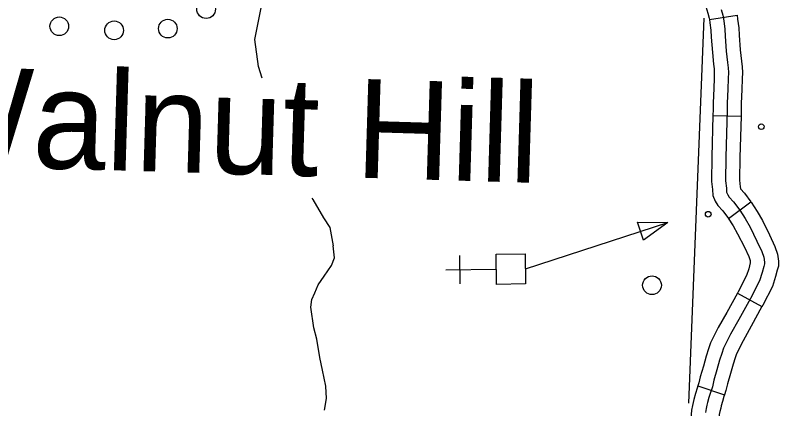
# Model space of a CAD drawing. Extents: x 653372 to 905732, y 627442 to 787275.
# Drawn here: x 722553 to 726614, y 759842 to 761946 of the extents above; entities that cross this region are included whole.
import ezdxf

# ---------------------------------------------------------------- set-up
doc = ezdxf.new("R2010")
doc.units = 0
for name, color, linetype in [('25', 7, 'Continuous'), ('32', 7, 'Continuous'), ('35', 7, 'Continuous'), ('5', 7, 'Continuous'), ('56', 7, 'Continuous'), ('57', 7, 'Continuous')]:
    doc.layers.add(name, color=color, linetype=linetype)

msp = doc.modelspace()

# ---------------------------------------------------------------- linework, layer by layer
at = {"layer": '32'}
for p, q in [((726264.3, 761922.8), (726412.4, 761946.2)), ((726283.8, 761410), (726433.7, 761406.1)), ((726366.7, 760858.7), (726486.6, 760948.9)), ((726414, 760460.5), (726545.6, 760388.4)), ((726203, 759965.3), (726345.2, 759917.6))]:
    msp.add_line(p, q, dxfattribs=at)
for points in [[(726211.6, 762073.5), (726239.8, 762015.5), (726242.1, 762008.5), (726245.6, 761993.2), (726255.9, 761957.5), (726263.1, 761930.4), (726264.3, 761922.8)], [(726328.2, 761977.5), (726336.6, 761945.8), (726341.4, 761915.5), (726346.5, 761872.1), (726348.9, 761833.5), (726355.1, 761753.9), (726361.8, 761693), (726364.5, 761665), (726365.9, 761639.1), (726365, 761608.1), (726363.3, 761551), (726359.9, 761475.5), (726359.6, 761440.9)], [(726412.4, 761946.2), (726415.7, 761925.7), (726421.2, 761878.9), (726423.7, 761838.7), (726429.8, 761760.9), (726436.4, 761700.8), (726439.4, 761670.7), (726441, 761640), (726439.9, 761605.8), (726438.2, 761548.2), (726434.9, 761473.5), (726434.6, 761439.6), (726433.7, 761406.1)], [(726264.3, 761922.8), (726267.1, 761905.2), (726271.8, 761865.4), (726274.1, 761828.3), (726280.4, 761746.8), (726287.2, 761685.2), (726289.7, 761659.4), (726290.8, 761638.3), (726290, 761610.3), (726288.3, 761553.8), (726284.9, 761477.5), (726284.6, 761442.2), (726283.8, 761410)], [(726359.6, 761440.9), (726353, 761187.8), (726350.7, 761061.3), (726355.2, 761021.9), (726356.7, 761000.2), (726362.7, 760986.5), (726370.2, 760973.4), (726393.7, 760947.7), (726426.7, 760903.8), (726456.1, 760858.6), (726481.9, 760813.5), (726518.9, 760738.7), (726545.1, 760682.9), (726554.9, 760651.8), (726559.2, 760626.7), (726558.9, 760616.7), (726554.9, 760602.5), (726546.7, 760570.6), (726532.5, 760525.3), (726484, 760432.1), (726422.7, 760320.2), (726378.2, 760241.5), (726340.2, 760165.8), (726330.8, 760138.2), (726319, 760102.1), (726304.6, 760050.4), (726288.6, 759994.4), (726280.4, 759960.3), (726270.2, 759929.9), (726262.2, 759902.2), (726254.3, 759875.3), (726251.7, 759861.1), (726247.6, 759844), (726243.4, 759822.7)], [(726283.8, 761410), (726278, 761189.5), (726275.6, 761057.7), (726280.5, 761015), (726282.8, 760982.1), (726295.6, 760952.8), (726309.2, 760929), (726335.9, 760899.7), (726366.7, 760858.7)], [(726433.7, 761406.1), (726428, 761186.1), (726425.7, 761064.9), (726429.9, 761028.8), (726430.6, 761018.9), (726431.2, 761017.8), (726451.5, 760995.6), (726486.6, 760948.9)], [(726487.7, 760947.4), (726488.7, 760946), (726520.1, 760897.6), (726548.1, 760848.8), (726586.5, 760771.3), (726615.1, 760710.2), (726628, 760669.4), (726634.3, 760631.9), (726633.5, 760605.2), (726627.3, 760583.1), (726618.9, 760550.1), (726602.1, 760496.5), (726550.1, 760396.7), (726545.6, 760388.4)], [(726364.7, 760861.5), (726392, 760819.5), (726415.7, 760778.1), (726451.4, 760706.1), (726475.1, 760655.5), (726481.8, 760634.2), (726483.3, 760625.2), (726482.4, 760621.9), (726474.6, 760591.1), (726462.9, 760554), (726417.8, 760467.4), (726414, 760460.5)], [(726414, 760460.5), (726357.2, 760356.7), (726312, 760276.8), (726270.9, 760194.9), (726259.7, 760162), (726247.2, 760123.9), (726232.4, 760070.7), (726216, 760013.4), (726208.3, 759981), (726203, 759965.3)], [(726545.6, 760388.4), (726488.3, 760283.7), (726444.4, 760206.2), (726409.5, 760136.8), (726401.9, 760114.5), (726390.8, 760080.4), (726376.8, 760030), (726361.2, 759975.3), (726352.6, 759939.6), (726345.2, 759917.6)], [(726203, 759965.3), (726198.6, 759952.2), (726190.2, 759923.3), (726181.2, 759892.7), (726178.3, 759876.5), (726174.3, 759860.1), (726169.3, 759834.4), (726166.6, 759811.8), (726165.5, 759773.7), (726167.2, 759742.7), (726171.7, 759707.1), (726184.7, 759662), (726215.7, 759567.8), (726240.7, 759499.2), (726270, 759409.4), (726270.3, 759408.5)], [(726345.2, 759917.6), (726341.8, 759907.5), (726334.2, 759881.2), (726327.4, 759858), (726325.1, 759845.7), (726320.9, 759828), (726317.6, 759811.1), (726316.4, 759800.8), (726315.6, 759775.6), (726316.7, 759756.4), (726319.1, 759737.5), (726328.1, 759706.2), (726357.4, 759617), (726382.5, 759548.2), (726412.1, 759457.5), (726411.9, 759458.2)]]:
    msp.add_lwpolyline(points, dxfattribs=at)
at = {"layer": '35'}
for points in [[(723872.5, 761610.4), (723853.2, 761672), (723834.7, 761816.2), (723861.5, 761949.3), (723880.9, 762050), (723896.5, 762134.4), (723921.4, 762205.5), (723959.5, 762276.2), (724028, 762385.2)], [(724139.3, 760968), (724143.6, 760961.7), (724201.1, 760863.7), (724235.4, 760810.4), (724253.6, 760713.4)], [(724206.1, 759834.7), (724217.8, 759896.4), (724213.2, 759963.4), (724196.2, 760048.4), (724181.5, 760116.3), (724165.3, 760214.2), (724149.1, 760275.1), (724134.3, 760384.7), (724138.9, 760427), (724154.6, 760462.4), (724172.2, 760504.4), (724204.6, 760550.8), (724244.4, 760608.5), (724259.8, 760648.7), (724253.6, 760713.4)]]:
    msp.add_lwpolyline(points, dxfattribs=at)
at = {"layer": '5'}
msp.add_lwpolyline([(726234.1, 761930.9), (726152.8, 759872.8)], dxfattribs=at)
at = {"layer": '56'}
for centre in [(723573.7, 761978.8), (722788.7, 761886.9), (723082, 761865.2), (723369, 761874.4), (725957.7, 760502.5)]:
    msp.add_circle(centre, 50, dxfattribs=at)
at = {"layer": '57'}
for p, q in [((725880.2, 760839.6), (726041.5, 760838.6)), ((725911.9, 760742.7), (725880.2, 760839.6)), ((726041.5, 760838.6), (725911.9, 760742.7)), ((724931.6, 760510.8), (724929.6, 760660.8)), ((724855.6, 760584.8), (725124.8, 760588.4))]:
    msp.add_line(p, q, dxfattribs=at)
msp.add_lwpolyline([(725280.8, 760590.2), (726041.5, 760838.6)], dxfattribs=at)
msp.add_lwpolyline([(725281.9, 760509.3), (725125.9, 760507.2), (725123.7, 760669), (725279.7, 760671.1)], close=True, dxfattribs=at)
for centre in [(726542, 761350.2), (726258.2, 760882.3)]:
    msp.add_circle(centre, 15, dxfattribs=at)

# ---------------------------------------------------------------- texts
at = {"layer": '25'}
msp.add_text('Walnut Hill', height=527.999, rotation=358.28, dxfattribs=at).set_placement((721974.6, 761150.4))

doc.saveas('drawing.dxf')
